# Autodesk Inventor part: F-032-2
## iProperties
Author: Ron Crain
Shininess: 85.0
Length Units: 11272
Angle Units: 11286
Time Units: 11279
Mass Units: 11290
Length Display Precision: 3
Angle Display Precision: 2
Compacted: True
PropertySet Name: _Private Model Information
Created: 2001-06
Part Number: F-032-2
Material: Stainless Steel, Austenitic
Description: FASTENER, SELF CLINCH, FLUSH, 10-32 UNF
Vendor: PENN ENG. & MFG
Document SubType Name: Modeling
Designer: Ron Crain
Control State: 0
Master: False
Checked Out: False
PropertySet Name: Design Tracking Control
Density: 8.03
Volumn: 0.1296629316058
Area: 3.1269348748049666
PropertySet Name: Model Information
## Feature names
1. Extrusion1
2. Extrusion2
